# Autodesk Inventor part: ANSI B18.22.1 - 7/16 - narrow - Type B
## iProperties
Comments: To add or edit properties for Autodesk Inventor files, use iProperties.
Created: 2005-05
Part Number: ANSI B18.22.1 - 7/16 - narrow - Type B
Vendor: Autodesk Inc.
Document SubType Name: Modeling
Designer: John Blackburn
Material: Default
Description: Washer B
Standard: ANSI B18.22.1
Alert: To add or edit properties for Autodesk Inventor files, use iProperties.
Control State: 0
Master: False
Checked Out: False
Shininess: 64.0
Length Units: 11272
Angle Units: 11279
Time Units: 11290
Mass Units: 11286
Length Display Precision: 3
Angle Display Precision: 2
Compacted: True
Classification: un/spsc 31161807
Density: 0.0
Volumn: 0.0
Area: 0.0
PropertySet Name: Model Information
Author: John Blackburn
Revision Number: 8
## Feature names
1. Body [Extrusion]
